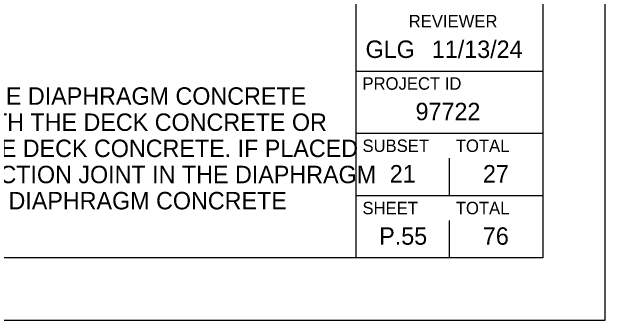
# Model space of a CAD drawing. Extents: x 0 to 34, y 0 to 22.
# Drawn here: x 29.233 to 34, y 0 to 2.475 of the extents above; entities that cross this region are included whole.
import ezdxf

# ---------------------------------------------------------------- set-up
doc = ezdxf.new("R2010")
doc.units = 0
for name, color, linetype in [('Default', 7, 'Continuous'), ('DV_X_Lot_Line', 7, 'Continuous'), ('RW_X_Esmt_SH', 7, 'Continuous'), ('SC_Scratch1', 7, 'Continuous')]:
    doc.layers.add(name, color=color, linetype=linetype)

msp = doc.modelspace()

# ---------------------------------------------------------------- linework, layer by layer
at = {"layer": 'DV_X_Lot_Line'}
msp.add_lwpolyline([(0, 0), (34, 0), (34, 22), (0, 22)], close=True, dxfattribs=at)
at = {"layer": 'RW_X_Esmt_SH'}
for p, q in [((32, 0.5), (32, 21.5)), ((32, 2), (33.5, 2)), ((32, 1.5), (33.5, 1.5)), ((32, 1), (33.5, 1))]:
    msp.add_line(p, q, dxfattribs=at)
msp.add_lwpolyline([(1.5, 21.5), (33.5, 21.5), (33.5, 0.5), (1.5, 0.5)], close=True, dxfattribs=at)
at = {"layer": 'SC_Scratch1'}
for p, q in [((32.75, 1), (32.75, 1.3)), ((32.75, 0.5), (32.75, 0.8)), ((32.375, 0.675), (32.375, 0.675))]:
    msp.add_line(p, q, dxfattribs=at)

# ---------------------------------------------------------------- texts
at = {"layer": 'Default'}
for s, p in [('3. ABUTMENT DIAPHRAGM CONCRETE: PLACE THE DIAPHRAGM CONCRETE ', (24.6391, 1.7293)), ('ENCASING THE STRUCTURAL MEMBER ENDS WITH THE DECK CONCRETE OR ', (24.6391, 1.5193)), ('AT LEAST 48 HOURS BEFORE PLACEMENT OF THE DECK CONCRETE. IF PLACED ', (24.6391, 1.3093)), ('SEPARATELY, LOCATE A HORIZONTAL CONSTRUCTION JOINT IN THE DIAPHRAGM ', (24.6391, 1.0993)), ('AS SHOWN ON SICD-1-96 AND PLACE REMAINING DIAPHRAGM CONCRETE ', (24.6391, 0.8893))]:
    msp.add_text(s, height=0.14, dxfattribs=at).set_placement(p)
at = {"layer": 'SC_Scratch1'}
for s, height, p in [('REVIEWER', 0.1, (32.4218, 2.35)), ('GLG', 0.14, (32.075, 2.105)), ('11/13/24', 0.14, (32.6078, 2.105)), ('PROJECT ID', 0.1, (32.05, 1.85)), ('97722', 0.14, (32.4768, 1.605)), ('SUBSET', 0.1, (32.05, 1.35)), ('TOTAL', 0.1, (32.8, 1.35)), ('21', 0.14, (32.2692, 1.105)), ('27', 0.14, (33.0183, 1.105)), ('SHEET', 0.1, (32.05, 0.85)), ('TOTAL', 0.1, (32.8, 0.85)), ('P.55', 0.14, (32.1848, 0.605)), ('76', 0.14, (33.0176, 0.605))]:
    msp.add_text(s, height=height, dxfattribs=at).set_placement(p)

doc.saveas('drawing.dxf')
